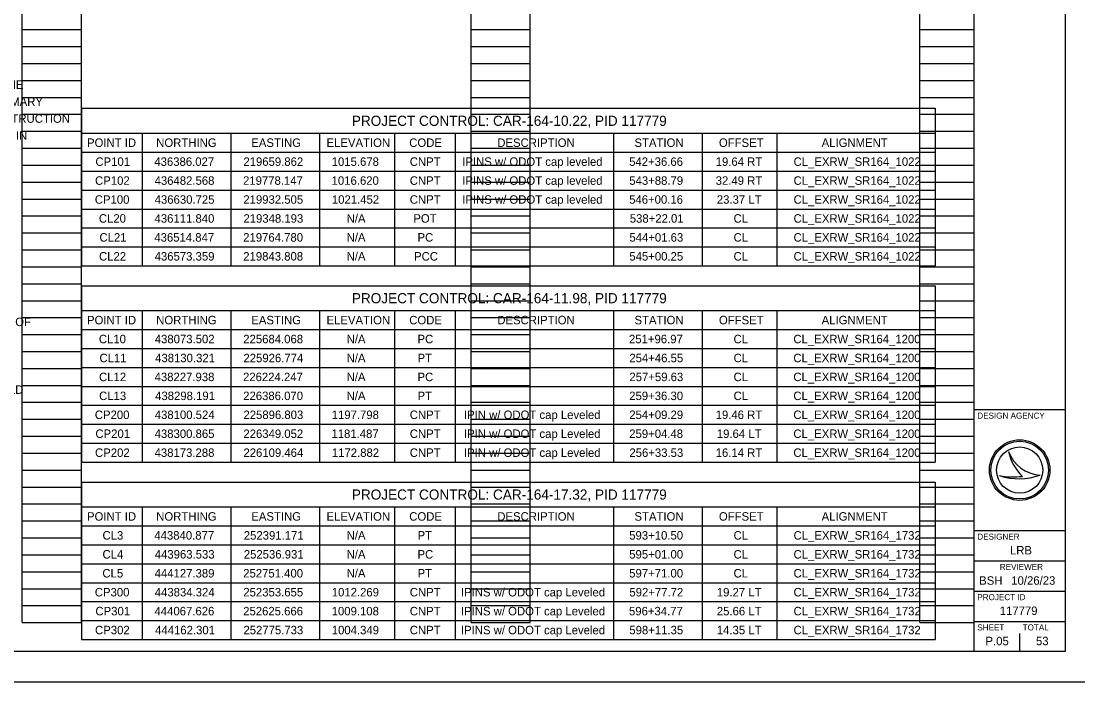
# Model space of a CAD drawing. Extents: x -6.7 to 44.8, y 0 to 42.6.
# Drawn here: x 16.24 to 33.71, y 0 to 10.92 of the extents above; entities that cross this region are included whole.
import ezdxf

# ---------------------------------------------------------------- set-up
doc = ezdxf.new("R2010")
doc.units = 0
for name, color, linetype in [('SH_Border', 7, 'Continuous'), ('SH_Cut_Line', 7, 'Continuous'), ('SH_Data', 7, 'Continuous'), ('SH_Text', 7, 'Continuous')]:
    doc.layers.add(name, color=color, linetype=linetype)

msp = doc.modelspace()

# ---------------------------------------------------------------- linework, layer by layer
at = {"layer": 'SH_Border'}
for p, q in [((32, 0.5), (32, 21.5)), ((32, 4.5), (33.5, 4.5)), ((32, 2.5), (33.5, 2.5)), ((32, 2), (33.5, 2)), ((32, 1.5), (33.5, 1.5)), ((32, 1), (33.5, 1))]:
    msp.add_line(p, q, dxfattribs=at)
msp.add_lwpolyline([(1.5, 21.5), (33.5, 21.5), (33.5, 0.5), (1.5, 0.5)], close=True, dxfattribs=at)
at = {"layer": 'SH_Cut_Line'}
msp.add_lwpolyline([(0, 0), (34, 0), (34, 22), (0, 22)], close=True, dxfattribs=at)
at = {"layer": 'SH_Data'}
for p, q in [((16.26, 0.98), (16.26, 21.14)), ((17.24, 0.98), (17.24, 21.14)), ((23.68, 0.98), (23.68, 21.14)), ((24.66, 0.98), (24.66, 21.14)), ((31.1, 0.98), (31.1, 21.14)), ((32, 0.98), (32, 21.14)), ((16.26, 10.78), (17.24, 10.78)), ((23.68, 10.78), (24.66, 10.78)), ((31.1, 10.78), (32, 10.78)), ((16.26, 10.5), (17.24, 10.5)), ((23.68, 10.5), (24.66, 10.5)), ((31.1, 10.5), (32, 10.5)), ((16.26, 10.22), (17.24, 10.22)), ((23.68, 10.22), (24.66, 10.22)), ((31.1, 10.22), (32, 10.22)), ((16.26, 9.94), (17.24, 9.94)), ((23.68, 9.94), (24.66, 9.94)), ((31.1, 9.94), (32, 9.94)), ((16.26, 9.66), (17.24, 9.66)), ((23.68, 9.66), (24.66, 9.66)), ((31.1, 9.66), (32, 9.66)), ((16.26, 9.38), (17.24, 9.38)), ((23.68, 9.38), (24.66, 9.38)), ((31.1, 9.38), (32, 9.38)), ((16.26, 9.1), (17.24, 9.1)), ((23.68, 9.1), (24.66, 9.1)), ((31.1, 9.1), (32, 9.1)), ((16.26, 8.82), (17.24, 8.82)), ((23.68, 8.82), (24.66, 8.82)), ((31.1, 8.82), (32, 8.82)), ((16.26, 8.54), (17.24, 8.54)), ((23.68, 8.54), (24.66, 8.54)), ((31.1, 8.54), (32, 8.54)), ((16.26, 8.26), (17.24, 8.26)), ((23.68, 8.26), (24.66, 8.26)), ((31.1, 8.26), (32, 8.26)), ((16.26, 7.98), (17.24, 7.98)), ((23.68, 7.98), (24.66, 7.98)), ((31.1, 7.98), (32, 7.98)), ((16.26, 7.7), (17.24, 7.7)), ((23.68, 7.7), (24.66, 7.7)), ((31.1, 7.7), (32, 7.7)), ((16.26, 7.42), (17.24, 7.42)), ((23.68, 7.42), (24.66, 7.42)), ((31.1, 7.42), (32, 7.42)), ((16.26, 7.14), (17.24, 7.14)), ((23.68, 7.14), (24.66, 7.14)), ((31.1, 7.14), (32, 7.14)), ((16.26, 6.86), (17.24, 6.86)), ((23.68, 6.86), (24.66, 6.86)), ((31.1, 6.86), (32, 6.86)), ((16.26, 6.58), (17.24, 6.58)), ((23.68, 6.58), (24.66, 6.58)), ((31.1, 6.58), (32, 6.58)), ((16.26, 6.3), (17.24, 6.3)), ((23.68, 6.3), (24.66, 6.3)), ((31.1, 6.3), (32, 6.3)), ((16.26, 6.02), (17.24, 6.02)), ((23.68, 6.02), (24.66, 6.02)), ((31.1, 6.02), (32, 6.02)), ((16.26, 5.74), (17.24, 5.74)), ((23.68, 5.74), (24.66, 5.74)), ((31.1, 5.74), (32, 5.74)), ((16.26, 5.46), (17.24, 5.46)), ((23.68, 5.46), (24.66, 5.46)), ((31.1, 5.46), (32, 5.46)), ((16.26, 5.18), (17.24, 5.18)), ((23.68, 5.18), (24.66, 5.18)), ((31.1, 5.18), (32, 5.18)), ((16.26, 4.9), (17.24, 4.9)), ((23.68, 4.9), (24.66, 4.9)), ((31.1, 4.9), (32, 4.9)), ((16.26, 4.62), (17.24, 4.62)), ((23.68, 4.62), (24.66, 4.62)), ((31.1, 4.62), (32, 4.62)), ((16.26, 4.34), (17.24, 4.34)), ((23.68, 4.34), (24.66, 4.34)), ((31.1, 4.34), (32, 4.34)), ((16.26, 4.06), (17.24, 4.06)), ((23.68, 4.06), (24.66, 4.06)), ((31.1, 4.06), (32, 4.06)), ((16.26, 3.78), (17.24, 3.78)), ((23.68, 3.78), (24.66, 3.78)), ((31.1, 3.78), (32, 3.78)), ((32.567, 3.81), (32.567, 3.81)), ((16.26, 3.5), (17.24, 3.5)), ((23.68, 3.5), (24.66, 3.5)), ((31.1, 3.5), (32, 3.5)), ((32.75, 3.5), (32.75, 3.5)), ((32.417, 3.41), (32.417, 3.41)), ((33.087, 3.419), (33.087, 3.419)), ((16.26, 3.22), (17.24, 3.22)), ((23.68, 3.22), (24.66, 3.22)), ((31.1, 3.22), (32, 3.22)), ((16.26, 2.94), (17.24, 2.94)), ((23.68, 2.94), (24.66, 2.94)), ((31.1, 2.94), (32, 2.94)), ((16.26, 2.66), (17.24, 2.66)), ((23.68, 2.66), (24.66, 2.66)), ((31.1, 2.66), (32, 2.66)), ((16.26, 2.38), (17.24, 2.38)), ((23.68, 2.38), (24.66, 2.38)), ((31.1, 2.38), (32, 2.38)), ((16.26, 2.1), (17.24, 2.1)), ((23.68, 2.1), (24.66, 2.1)), ((31.1, 2.1), (32, 2.1)), ((16.26, 1.82), (17.24, 1.82)), ((23.68, 1.82), (24.66, 1.82)), ((31.1, 1.82), (32, 1.82)), ((16.26, 1.54), (17.24, 1.54)), ((23.68, 1.54), (24.66, 1.54)), ((31.1, 1.54), (32, 1.54)), ((16.26, 1.26), (17.24, 1.26)), ((23.68, 1.26), (24.66, 1.26)), ((31.1, 1.26), (32, 1.26)), ((16.26, 0.98), (17.24, 0.98)), ((23.68, 0.98), (24.66, 0.98)), ((31.1, 0.98), (32, 0.98)), ((32.75, 0.5), (32.75, 0.8)), ((32.375, 0.675), (32.375, 0.675))]:
    msp.add_line(p, q, dxfattribs=at)
for radius in [0.5, 0.477, 0.477, 0.382]:
    msp.add_circle((32.75, 3.5), radius, dxfattribs=at)
for centre, radius, start, end in [((33.116, 3.998), 0.58, 198.9257, 198.9319), ((33.347, 3.97), 0.796, 191.6379, 191.6421), ((33.116, 3.998), 0.58, 198.9319, 267.1657), ((33.347, 3.97), 0.796, 191.6421, 226.0947), ((32.739, 4.37), 1.013, 251.4576, 290.0832), ((32.648, 4.654), 1.266, 259.4964, 259.4995), ((32.739, 4.37), 1.013, 251.4527, 251.4576), ((32.648, 4.654), 1.266, 259.4995, 276.6672)]:
    msp.add_arc(centre, radius, start, end, dxfattribs=at)
at = {"layer": 'SH_Text'}
for p, q in [((17.24, 9.479), (31.355, 9.479)), ((17.24, 9.479), (17.24, 6.876)), ((31.355, 9.479), (31.355, 6.876)), ((17.24, 9.067), (31.355, 9.067)), ((18.245, 9.067), (18.245, 6.876)), ((19.711, 9.067), (19.711, 6.876)), ((21.176, 9.067), (21.176, 6.876)), ((22.412, 9.067), (22.412, 6.876)), ((23.416, 9.067), (23.416, 6.876)), ((26.035, 9.067), (26.035, 6.876)), ((27.501, 9.067), (27.501, 6.876)), ((28.736, 9.067), (28.736, 6.876)), ((17.24, 8.754), (31.355, 8.754)), ((17.24, 8.441), (31.355, 8.441)), ((17.24, 8.128), (31.355, 8.128)), ((17.24, 7.815), (31.355, 7.815)), ((17.24, 7.502), (31.355, 7.502)), ((17.24, 7.189), (31.355, 7.189)), ((17.24, 6.876), (31.355, 6.876)), ((17.24, 6.547), (31.355, 6.547)), ((17.24, 6.547), (17.24, 3.632)), ((31.355, 6.547), (31.355, 3.632)), ((17.24, 6.135), (31.355, 6.135)), ((18.245, 6.135), (18.245, 3.632)), ((19.711, 6.135), (19.711, 3.632)), ((21.176, 6.135), (21.176, 3.632)), ((22.412, 6.135), (22.412, 3.632)), ((23.416, 6.135), (23.416, 3.632)), ((26.035, 6.135), (26.035, 3.632)), ((27.501, 6.135), (27.501, 3.632)), ((28.736, 6.135), (28.736, 3.632)), ((17.24, 5.822), (31.355, 5.822)), ((17.24, 5.509), (31.355, 5.509)), ((17.24, 5.196), (31.355, 5.196)), ((17.24, 4.884), (31.355, 4.884)), ((17.24, 4.571), (31.355, 4.571)), ((17.24, 4.258), (31.355, 4.258)), ((17.24, 3.945), (31.355, 3.945)), ((17.24, 3.632), (31.355, 3.632)), ((17.24, 3.302), (31.355, 3.302)), ((17.24, 3.302), (17.24, 0.7)), ((31.355, 3.302), (31.355, 0.7)), ((17.24, 2.891), (31.355, 2.891)), ((18.245, 2.891), (18.245, 0.7)), ((19.711, 2.891), (19.711, 0.7)), ((21.176, 2.891), (21.176, 0.7)), ((22.412, 2.891), (22.412, 0.7)), ((23.416, 2.891), (23.416, 0.7)), ((26.035, 2.891), (26.035, 0.7)), ((27.501, 2.891), (27.501, 0.7)), ((28.736, 2.891), (28.736, 0.7)), ((17.24, 2.578), (31.355, 2.578)), ((17.24, 2.265), (31.355, 2.265)), ((17.24, 1.952), (31.355, 1.952)), ((17.24, 1.639), (31.355, 1.639)), ((17.24, 1.326), (31.355, 1.326)), ((17.24, 1.013), (31.355, 1.013)), ((17.24, 0.7), (31.355, 0.7))]:
    msp.add_line(p, q, dxfattribs=at)

# ---------------------------------------------------------------- texts
at = {"layer": 'SH_Data'}
for s, height, p in [('DESIGN AGENCY', 0.1, (32.05, 4.35)), ('DESIGNER', 0.1, (32.05, 2.35)), ('LRB', 0.14, (32.589, 2.105)), ('REVIEWER', 0.1, (32.422, 1.85)), ('BSH', 0.14, (32.08, 1.605)), ('10/26/23', 0.14, (32.611, 1.605)), ('PROJECT ID', 0.1, (32.05, 1.35)), ('117779', 0.14, (32.42, 1.105)), ('SHEET', 0.1, (32.05, 0.85)), ('TOTAL', 0.1, (32.8, 0.85)), ('P.05', 0.14, (32.185, 0.605)), ('53', 0.14, (33.02, 0.605))]:
    msp.add_text(s, height=height, dxfattribs=at).set_placement(p)
at = {"layer": 'SH_Text'}
for s, height, p in [('USE THE POSITIONING METHODS AND MONUMENT TYPE USED IN THE ', 0.14, (9.82, 9.8)), ('ORIGINAL SURVEY TO RESTORE ALL MONUMENTS RELATED TO PRIMARY ', 0.14, (9.82, 9.52)), ('PROJECT CONTROL THAT ARE DAMAGED OR DESTROYED BY CONSTRUCTION ', 0.14, (9.82, 9.24)), ('PROJECT CONTROL: CAR-164-10.22, PID 117779', 0.168, (21.709, 9.189)), ('ACTIVITIES. RESTORE THE DAMAGED OR DESTROYED MONUMENTS IN ', 0.14, (9.82, 8.96)), ('POINT ID', 0.14, (17.331, 8.841)), ('NORTHING', 0.14, (18.475, 8.841)), ('EASTING', 0.14, (20.047, 8.841)), ('ELEVATION', 0.14, (21.291, 8.841)), ('CODE', 0.14, (22.658, 8.841)), ('DESCRIPTION', 0.14, (24.114, 8.841)), ('STATION', 0.14, (26.382, 8.841)), ('OFFSET', 0.14, (27.778, 8.841)), ('ALIGNMENT', 0.14, (29.476, 8.841)), ('CP101', 0.14, (17.47, 8.528)), ('436386.027', 0.14, (18.444, 8.528)), ('219659.862', 0.14, (19.916, 8.528)), ('1015.678', 0.14, (21.376, 8.528)), ('CNPT', 0.14, (22.667, 8.528)), ('IPINS w/ ODOT cap leveled', 0.14, (23.534, 8.528)), ('542+36.66', 0.14, (26.294, 8.528)), ('19.64 RT', 0.14, (27.724, 8.528)), ('CL_EXRW_SR164_1022', 0.14, (29.012, 8.528)), ('CP102', 0.14, (17.464, 8.215)), ('436482.568', 0.14, (18.448, 8.215)), ('219778.147', 0.14, (19.91, 8.215)), ('1016.620', 0.14, (21.375, 8.215)), ('CNPT', 0.14, (22.667, 8.215)), ('IPINS w/ ODOT cap leveled', 0.14, (23.534, 8.215)), ('543+88.79', 0.14, (26.296, 8.215)), ('32.49 RT', 0.14, (27.724, 8.215)), ('CL_EXRW_SR164_1022', 0.14, (29.012, 8.215)), ('CP100', 0.14, (17.46, 7.902)), ('436630.725', 0.14, (18.449, 7.902)), ('219932.505', 0.14, (19.915, 7.902)), ('1021.452', 0.14, (21.379, 7.902)), ('CNPT', 0.14, (22.667, 7.902)), ('IPINS w/ ODOT cap leveled', 0.14, (23.534, 7.902)), ('546+00.16', 0.14, (26.294, 7.902)), ('23.37 LT', 0.14, (27.743, 7.902)), ('CL_EXRW_SR164_1022', 0.14, (29.012, 7.902)), ('CL20', 0.14, (17.527, 7.589)), ('436111.840', 0.14, (18.447, 7.589)), ('219348.193', 0.14, (19.917, 7.589)), ('N/A', 0.14, (21.623, 7.589)), ('POT', 0.14, (22.726, 7.589)), ('538+22.01', 0.14, (26.304, 7.589)), ('CL', 0.14, (28.02, 7.589)), ('CL_EXRW_SR164_1022', 0.14, (29.012, 7.589)), ('CL21', 0.14, (17.537, 7.276)), ('436514.847', 0.14, (18.444, 7.276)), ('219764.780', 0.14, (19.913, 7.276)), ('N/A', 0.14, (21.623, 7.276)), ('PC', 0.14, (22.795, 7.276)), ('544+01.63', 0.14, (26.298, 7.276)), ('CL', 0.14, (28.02, 7.276)), ('CL_EXRW_SR164_1022', 0.14, (29.012, 7.276)), ('CL22', 0.14, (17.53, 6.963)), ('436573.359', 0.14, (18.449, 6.963)), ('219843.808', 0.14, (19.914, 6.963)), ('N/A', 0.14, (21.623, 6.963)), ('PCC', 0.14, (22.738, 6.963)), ('545+00.25', 0.14, (26.297, 6.963)), ('CL', 0.14, (28.02, 6.963)), ('CL_EXRW_SR164_1022', 0.14, (29.012, 6.963)), ('PROJECT CONTROL: CAR-164-11.98, PID 117779', 0.168, (21.709, 6.257)), ('ACCEPTANCE, PERFORM AN INSPECTION WITH REPRESENTATIVES  OF ', 0.14, (9.82, 5.88)), ('POINT ID', 0.14, (17.331, 5.909)), ('NORTHING', 0.14, (18.475, 5.909)), ('EASTING', 0.14, (20.047, 5.909)), ('ELEVATION', 0.14, (21.291, 5.909)), ('CODE', 0.14, (22.658, 5.909)), ('DESCRIPTION', 0.14, (24.114, 5.909)), ('STATION', 0.14, (26.382, 5.909)), ('OFFSET', 0.14, (27.778, 5.909)), ('ALIGNMENT', 0.14, (29.476, 5.909)), ('CL10', 0.14, (17.527, 5.596)), ('438073.502', 0.14, (18.451, 5.596)), ('225684.068', 0.14, (19.914, 5.596)), ('N/A', 0.14, (21.623, 5.596)), ('PC', 0.14, (22.795, 5.596)), ('251+96.97', 0.14, (26.291, 5.596)), ('CL', 0.14, (28.02, 5.596)), ('CL_EXRW_SR164_1200', 0.14, (29.009, 5.596)), ('CL11', 0.14, (17.537, 5.283)), ('438130.321', 0.14, (18.457, 5.283)), ('225926.774', 0.14, (19.917, 5.283)), ('N/A', 0.14, (21.623, 5.283)), ('PT', 0.14, (22.796, 5.283)), ('254+46.55', 0.14, (26.297, 5.283)), ('CL', 0.14, (28.02, 5.283)), ('CL_EXRW_SR164_1200', 0.14, (29.009, 5.283)), ('CL12', 0.14, (17.53, 4.97)), ('438227.938', 0.14, (18.448, 4.97)), ('226224.247', 0.14, (19.91, 4.97)), ('N/A', 0.14, (21.623, 4.97)), ('PC', 0.14, (22.795, 4.97)), ('257+59.63', 0.14, (26.298, 4.97)), ('CL', 0.14, (28.02, 4.97)), ('CL_EXRW_SR164_1200', 0.14, (29.009, 4.97)), ('CONDUITS AND THEIR APPURTENANCES IS DETERMINED FROM FIELD  ', 0.14, (9.82, 4.76)), ('CL13', 0.14, (17.531, 4.657)), ('438298.191', 0.14, (18.457, 4.657)), ('226386.070', 0.14, (19.913, 4.657)), ('N/A', 0.14, (21.623, 4.657)), ('PT', 0.14, (22.796, 4.657)), ('259+36.30', 0.14, (26.295, 4.657)), ('CL', 0.14, (28.02, 4.657)), ('CL_EXRW_SR164_1200', 0.14, (29.009, 4.657)), ('CP200', 0.14, (17.46, 4.344)), ('438100.524', 0.14, (18.451, 4.344)), ('225896.803', 0.14, (19.917, 4.344)), ('1197.798', 0.14, (21.376, 4.344)), ('CNPT', 0.14, (22.667, 4.344)), ('IPIN w/ ODOT cap Leveled', 0.14, (23.563, 4.344)), ('254+09.29', 0.14, (26.296, 4.344)), ('19.46 RT', 0.14, (27.724, 4.344)), ('CL_EXRW_SR164_1200', 0.14, (29.009, 4.344)), ('CP201', 0.14, (17.47, 4.031)), ('438300.865', 0.14, (18.449, 4.031)), ('226349.052', 0.14, (19.916, 4.031)), ('1181.487', 0.14, (21.372, 4.031)), ('CNPT', 0.14, (22.667, 4.031)), ('IPIN w/ ODOT cap Leveled', 0.14, (23.563, 4.031)), ('259+04.48', 0.14, (26.295, 4.031)), ('19.64 LT', 0.14, (27.743, 4.031)), ('CL_EXRW_SR164_1200', 0.14, (29.009, 4.031)), ('CP202', 0.14, (17.464, 3.718)), ('438173.288', 0.14, (18.448, 3.718)), ('226109.464', 0.14, (19.917, 3.718)), ('1172.882', 0.14, (21.379, 3.718)), ('CNPT', 0.14, (22.667, 3.718)), ('IPIN w/ ODOT cap Leveled', 0.14, (23.563, 3.718)), ('256+33.53', 0.14, (26.298, 3.718)), ('16.14 RT', 0.14, (27.724, 3.718)), ('CL_EXRW_SR164_1200', 0.14, (29.009, 3.718)), ('PROJECT CONTROL: CAR-164-17.32, PID 117779', 0.168, (21.709, 3.012)), ('POINT ID', 0.14, (17.331, 2.664)), ('NORTHING', 0.14, (18.475, 2.664)), ('EASTING', 0.14, (20.047, 2.664)), ('ELEVATION', 0.14, (21.291, 2.664)), ('CODE', 0.14, (22.658, 2.664)), ('DESCRIPTION', 0.14, (24.114, 2.664)), ('STATION', 0.14, (26.382, 2.664)), ('OFFSET', 0.14, (27.778, 2.664)), ('ALIGNMENT', 0.14, (29.476, 2.664)), ('CL3', 0.14, (17.587, 2.351)), ('443840.877', 0.14, (18.444, 2.351)), ('252391.171', 0.14, (19.923, 2.351)), ('N/A', 0.14, (21.623, 2.351)), ('PT', 0.14, (22.796, 2.351)), ('593+10.50', 0.14, (26.295, 2.351)), ('CL', 0.14, (28.02, 2.351)), ('CL_EXRW_SR164_1732', 0.14, (29.012, 2.351)), ('CL4', 0.14, (17.587, 2.038)), ('443963.533', 0.14, (18.451, 2.038)), ('252536.931', 0.14, (19.923, 2.038)), ('N/A', 0.14, (21.623, 2.038)), ('PC', 0.14, (22.795, 2.038)), ('595+01.00', 0.14, (26.295, 2.038)), ('CL', 0.14, (28.02, 2.038)), ('CL_EXRW_SR164_1732', 0.14, (29.012, 2.038)), ('CL5', 0.14, (17.585, 1.725)), ('444127.389', 0.14, (18.449, 1.725)), ('252751.400', 0.14, (19.913, 1.725)), ('N/A', 0.14, (21.623, 1.725)), ('PT', 0.14, (22.796, 1.725)), ('597+71.00', 0.14, (26.295, 1.725)), ('CL', 0.14, (28.02, 1.725)), ('CL_EXRW_SR164_1732', 0.14, (29.012, 1.725)), ('CP300', 0.14, (17.46, 1.412)), ('443834.324', 0.14, (18.451, 1.412)), ('252353.655', 0.14, (19.915, 1.412)), ('1012.269', 0.14, (21.377, 1.412)), ('CNPT', 0.14, (22.667, 1.412)), ('IPINS w/ ODOT cap Leveled', 0.14, (23.513, 1.412)), ('592+77.72', 0.14, (26.298, 1.412)), ('19.27 LT', 0.14, (27.743, 1.412)), ('CL_EXRW_SR164_1732', 0.14, (29.012, 1.412)), ('CP301', 0.14, (17.47, 1.099)), ('444067.626', 0.14, (18.447, 1.099)), ('252625.666', 0.14, (19.913, 1.099)), ('1009.108', 0.14, (21.376, 1.099)), ('CNPT', 0.14, (22.667, 1.099)), ('IPINS w/ ODOT cap Leveled', 0.14, (23.513, 1.099)), ('596+34.77', 0.14, (26.291, 1.099)), ('25.66 LT', 0.14, (27.743, 1.099)), ('CL_EXRW_SR164_1732', 0.14, (29.012, 1.099)), ('CP302', 0.14, (17.464, 0.786)), ('444162.301', 0.14, (18.457, 0.786)), ('252775.733', 0.14, (19.917, 0.786)), ('1004.349', 0.14, (21.377, 0.786)), ('CNPT', 0.14, (22.667, 0.786)), ('IPINS w/ ODOT cap Leveled', 0.14, (23.513, 0.786)), ('598+11.35', 0.14, (26.297, 0.786)), ('14.35 LT', 0.14, (27.743, 0.786)), ('CL_EXRW_SR164_1732', 0.14, (29.012, 0.786))]:
    msp.add_text(s, height=height, dxfattribs=at).set_placement(p)

doc.saveas('drawing.dxf')
